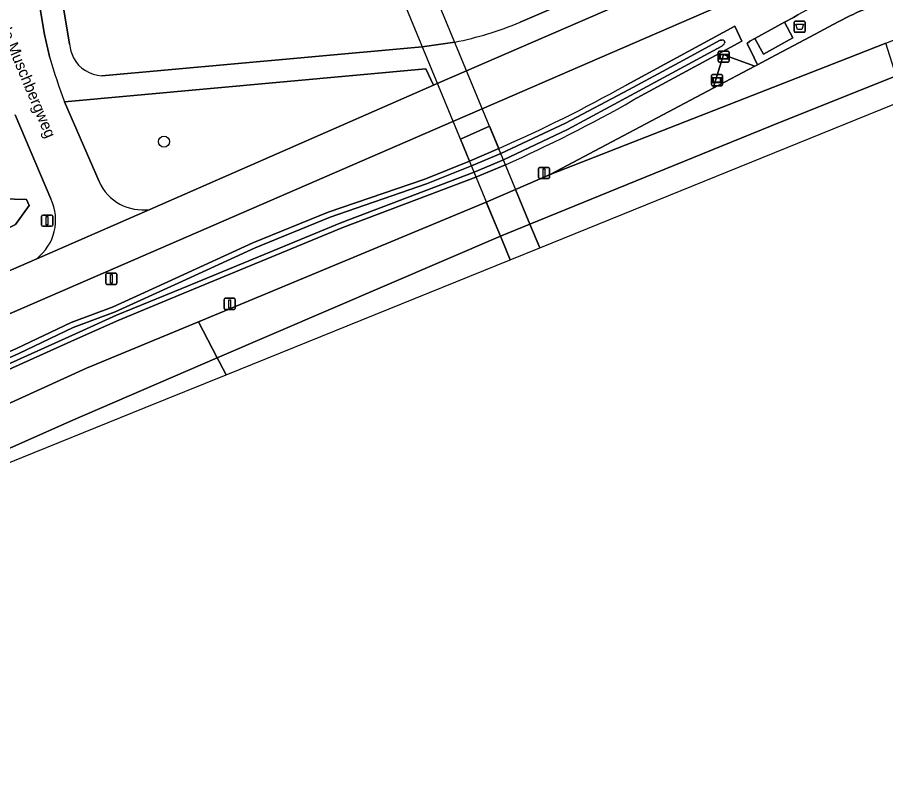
# Model space of a CAD drawing. Extents: x 162722 to 165104, y 384719 to 386284.
# Drawn here: x 164185 to 164262.4, y 384936.5 to 385003.6 of the extents above; entities that cross this region are included whole.
import ezdxf

# ---------------------------------------------------------------- set-up
doc = ezdxf.new("R2010")
doc.units = 0
for name, color, linetype in [('IMGEO_Afvalbak', 7, 'Continuous'), ('IMGEO_Berm_groen', 7, 'Continuous'), ('IMGEO_Boom', 7, 'Continuous'), ('IMGEO_Dek', 7, 'Continuous'), ('IMGEO_Fietspad_gesloten', 7, 'Continuous'), ('IMGEO_Groenvoorziening', 7, 'Continuous'), ('IMGEO_Informatiebord', 7, 'Continuous'), ('IMGEO_Lichtmast', 7, 'Continuous'), ('IMGEO_Oever', 7, 'Continuous'), ('IMGEO_Openbare_ruimte_label', 7, 'Continuous'), ('IMGEO_OVBaan_open', 7, 'Continuous'), ('IMGEO_Pijler', 7, 'Continuous'), ('IMGEO_Rijbaan_lokaal_open', 7, 'Continuous'), ('IMGEO_Rijbaan_regionaal_gesloten', 7, 'Continuous'), ('IMGEO_Verkeersbordpaal', 7, 'Continuous'), ('IMGEO_Voetpad_open', 7, 'Continuous'), ('IMGEO_Waterloop', 7, 'Continuous')]:
    doc.layers.add(name, color=color, linetype=linetype)

msp = doc.modelspace()

# ---------------------------------------------------------------- linework, layer by layer
at = {"layer": 'IMGEO_Afvalbak'}
for p, q in [((164254.24, 385002.368), (164254.24, 385003.168)), ((164254.24, 385003.168), (164254.24, 385002.368)), ((164254.34, 385003.268), (164255.13, 385003.268)), ((164255.13, 385003.268), (164254.34, 385003.268)), ((164255.23, 385003.168), (164255.23, 385002.368)), ((164255.23, 385002.368), (164255.23, 385003.168)), ((164255.13, 385002.268), (164254.34, 385002.268)), ((164254.34, 385002.268), (164255.13, 385002.268))]:
    msp.add_line(p, q, dxfattribs=at)
msp.add_lwpolyline([(164254.383, 385002.982), (164255.087, 385002.982), (164254.938, 385002.512), (164254.532, 385002.512), (164254.383, 385002.982)], dxfattribs=at)
for centre, start, end in [((164254.34, 385003.168), 90, 180), ((164254.34, 385003.168), 90, 180), ((164255.13, 385003.168), 0, 90), ((164255.13, 385003.168), 360, 90), ((164254.34, 385002.368), 180, 270), ((164254.34, 385002.368), 180, 270), ((164255.13, 385002.368), 270, 0), ((164255.13, 385002.368), 270, 0)]:
    msp.add_arc(centre, 0.1, start, end, dxfattribs=at)
at = {"layer": 'IMGEO_Berm_groen'}
for points in [[(164257.459, 385008.904), (164236.917, 385000), (164226.457, 384995.466), (164223.851, 384994.337), (164174.926, 384973.13)], [(164170.65, 384962.991), (164191.19, 384972.345), (164201.175, 384976.496), (164226.817, 384987.156), (164229.43, 384988.27), (164232.508, 384989.603), (164247.035, 384997.295), (164247.859, 385000), (164247.944, 385000.279), (164248.701, 385000), (164250.731, 384999.252), (164250.978, 384999.383), (164250.681, 385000), (164250.064, 385001.28), (164250.281, 385001.478), (164250.744, 385001.727), (164253.379, 385003.161), (164254.17, 385003.591), (164254.584, 385003.832)], [(164239.27, 384997.566), (164243.767, 385000), (164248.945, 385002.803), (164249.58, 385001.482), (164246.849, 385000), (164239.88, 384996.219)], [(164188.037, 384987.425), (164184.844, 384994.922)], [(163914.436, 384836.893), (163949.636, 384856.503), (163973.819, 384869.778), (164000, 384884.149), (164013.236, 384891.063), (164022.225, 384895.944), (164051.682, 384911.299), (164065.065, 384918.062), (164110.825, 384940.537), (164141.781, 384954.8), (164143.407, 384955.639), (164157.246, 384961.665), (164184.977, 384974.098), (164189.827, 384976.411), (164193.585, 384977.81), (164199.165, 384980.364), (164206.029, 384983.505), (164212.733, 384986.251), (164221.342, 384989.201), (164225.31, 384990.805), (164224.511, 384992.738), (164227.098, 384993.913), (164227.922, 384991.919)], [(164228.517, 384990.478), (164225.9, 384989.377), (164214.028, 384984.88), (164199.858, 384979.031), (164194.068, 384976.641), (164190.414, 384974.994), (164164.458, 384963.293), (164143.813, 384954.267), (164142.441, 384953.403), (164125.834, 384945.724), (164092.923, 384929.936), (164061.637, 384914.529), (164036.116, 384901.563), (164011.738, 384888.674), (164000, 384882.305), (163974.591, 384868.517), (163970.141, 384866.102), (163854.543, 384802.202), (163834.335, 384791.252), (163820.765, 384784.53), (163800.899, 384775.69)], [(164029.893, 384905.296), (164057.852, 384919.483), (164097.492, 384939.034), (164124.664, 384953.575), (164138.961, 384960.973), (164173.572, 384976.374), (164186.765, 384982.108)]]:
    msp.add_lwpolyline(points, dxfattribs=at)
msp.add_lwpolyline([(164140.35, 384963.895), (164139.999, 384964.462), (164141.087, 384966.275), (164183.725, 384987.45), (164185.859, 384987.374), (164186.107, 384986.836), (164184.89, 384985.145), (164141.803, 384963.834)], close=True, dxfattribs=at)
for centre, radius, start, end in [((164174.959, 385112.576), 131.769, 293.69908, 299.2127), ((164178.949, 385102.703), 122.685, 293.83045, 299.77868), ((164184.075, 384985.562), 4.378, 307.91124, 25.18045)]:
    msp.add_arc(centre, radius, start, end, dxfattribs=at)
at = {"layer": 'IMGEO_Boom'}
msp.add_circle((164198.104, 384992.531), 0.489, dxfattribs=at)
at = {"layer": 'IMGEO_Dek'}
msp.add_lwpolyline([(164231.573, 384983.081), (164220.787, 385009.193), (164220.592, 385009.115), (164220.399, 385009.469), (164218.209, 385008.591), (164218.345, 385008.216), (164218.15, 385008.138), (164228.941, 384982.015)], close=True, dxfattribs=at)
at = {"layer": 'IMGEO_Fietspad_gesloten'}
msp.add_lwpolyline([(164127.585, 384951.111), (164140.511, 384957.62), (164174.926, 384973.13), (164223.851, 384994.337), (164226.457, 384995.466), (164236.917, 385000), (164257.459, 385008.904), (164259.266, 385009.7), (164257.963, 385012.93), (164249.613, 385009.488), (164247.774, 385008.689), (164227.726, 385000), (164225.061, 384998.845), (164222.455, 384997.716), (164222.114, 384997.568), (164196.835, 384986.501), (164186.765, 384982.108), (164173.572, 384976.374), (164138.961, 384960.973), (164124.664, 384953.575), (164097.492, 384939.034)], dxfattribs=at)
at = {"layer": 'IMGEO_Groenvoorziening'}
for points in [[(164194.294, 385007.945), (164191.639, 385014.785), (164190.662, 385021.427), (164185.711, 385028.348), (164187.966, 385011.698), (164188.163, 385010.392), (164189.7, 385001.218)], [(164229.825, 385003.177), (164255.518, 385014.18)], [(164192.581, 384998.398), (164210.287, 385000), (164221.107, 385000.979), (164224.007, 385001.397)], [(164196.835, 384986.501), (164222.114, 384997.568), (164221.419, 384999.011), (164189.254, 384996.082), (164192.319, 384988.97)]]:
    msp.add_lwpolyline(points, dxfattribs=at)
for centre, radius, start, end in [((164218.363, 385030.243), 29.393, 281.07064, 292.95203), ((164192.699, 385001.412), 3.005, 183.6966, 208.02016), ((164192.712, 385001.412), 3.017, 207.91035, 267.50775), ((164196.205, 384990.713), 4.259, 204.15637, 278.51076)]:
    msp.add_arc(centre, radius, start, end, dxfattribs=at)
at = {"layer": 'IMGEO_Informatiebord'}
for p, q in [((164247.475, 384999.701), (164247.475, 385000.501)), ((164247.475, 385000.501), (164247.475, 384999.701)), ((164247.575, 385000.601), (164248.365, 385000.601)), ((164248.365, 385000.601), (164247.575, 385000.601)), ((164248.465, 385000.501), (164248.465, 384999.701)), ((164248.465, 384999.701), (164248.465, 385000.501)), ((164248.365, 384999.601), (164247.575, 384999.601)), ((164247.575, 384999.601), (164248.365, 384999.601)), ((164246.967, 384998.513), (164247.757, 384998.513)), ((164247.757, 384998.513), (164246.967, 384998.513)), ((164246.867, 384997.613), (164246.867, 384998.413)), ((164246.867, 384998.413), (164246.867, 384997.613)), ((164247.857, 384998.413), (164247.857, 384997.613)), ((164247.857, 384997.613), (164247.857, 384998.413)), ((164247.757, 384997.513), (164246.967, 384997.513)), ((164246.967, 384997.513), (164247.757, 384997.513))]:
    msp.add_line(p, q, dxfattribs=at)
for points in [[(164247.576, 385000.333), (164248.364, 385000.333), (164248.364, 384999.869), (164247.576, 384999.869), (164247.576, 385000.333)], [(164247.641, 385000.268), (164247.641, 384999.934), (164248.299, 384999.934), (164248.299, 385000.268), (164247.641, 385000.268)], [(164246.968, 384998.245), (164247.756, 384998.245), (164247.756, 384997.781), (164246.968, 384997.781), (164246.968, 384998.245)], [(164247.033, 384998.18), (164247.033, 384997.846), (164247.691, 384997.846), (164247.691, 384998.18), (164247.033, 384998.18)]]:
    msp.add_lwpolyline(points, dxfattribs=at)
for centre, start, end in [((164247.575, 385000.501), 90, 180), ((164247.575, 385000.501), 90, 180), ((164248.365, 385000.501), 0, 90), ((164248.365, 385000.501), 360, 90), ((164247.575, 384999.701), 180, 270), ((164247.575, 384999.701), 180, 270), ((164248.365, 384999.701), 270, 0), ((164248.365, 384999.701), 270, 0), ((164246.967, 384998.413), 90, 180), ((164246.967, 384998.413), 90, 180), ((164247.757, 384998.413), 0, 90), ((164247.757, 384998.413), 360, 90), ((164246.967, 384997.613), 180, 270), ((164246.967, 384997.613), 180, 270), ((164247.757, 384997.613), 270, 0), ((164247.757, 384997.613), 270, 0)]:
    msp.add_arc(centre, 0.1, start, end, dxfattribs=at)
at = {"layer": 'IMGEO_Lichtmast'}
for p, q in [((164231.468, 384989.34), (164231.468, 384990.14)), ((164231.468, 384990.14), (164231.468, 384989.34)), ((164231.568, 384990.24), (164232.358, 384990.24)), ((164232.358, 384990.24), (164231.568, 384990.24)), ((164232.458, 384990.14), (164232.458, 384989.34)), ((164232.458, 384989.34), (164232.458, 384990.14)), ((164232.358, 384989.24), (164231.568, 384989.24)), ((164231.568, 384989.24), (164232.358, 384989.24)), ((164203.463, 384977.679), (164203.463, 384978.479)), ((164203.463, 384978.479), (164203.463, 384977.679)), ((164203.563, 384978.579), (164204.353, 384978.579)), ((164204.353, 384978.579), (164203.563, 384978.579)), ((164204.453, 384978.479), (164204.453, 384977.679)), ((164204.453, 384977.679), (164204.453, 384978.479)), ((164204.353, 384977.579), (164203.563, 384977.579)), ((164203.563, 384977.579), (164204.353, 384977.579))]:
    msp.add_line(p, q, dxfattribs=at)
for points in [[(164231.888, 384990.115), (164232.038, 384990.115), (164232.038, 384989.365), (164231.888, 384989.365), (164231.888, 384990.115)], [(164203.883, 384978.454), (164204.033, 384978.454), (164204.033, 384977.704), (164203.883, 384977.704), (164203.883, 384978.454)]]:
    msp.add_lwpolyline(points, dxfattribs=at)
for centre, start, end in [((164231.568, 384990.14), 90, 180), ((164231.568, 384990.14), 90, 180), ((164232.358, 384990.14), 0, 90), ((164232.358, 384990.14), 360, 90), ((164231.568, 384989.34), 180, 270), ((164231.568, 384989.34), 180, 270), ((164232.358, 384989.34), 270, 0), ((164232.358, 384989.34), 270, 0), ((164203.563, 384978.479), 90, 180), ((164203.563, 384978.479), 90, 180), ((164204.353, 384978.479), 0, 90), ((164204.353, 384978.479), 360, 90), ((164203.563, 384977.679), 180, 270), ((164203.563, 384977.679), 180, 270), ((164204.353, 384977.679), 270, 0), ((164204.353, 384977.679), 270, 0)]:
    msp.add_arc(centre, 0.1, start, end, dxfattribs=at)
at = {"layer": 'IMGEO_Oever'}
for points in [[(164239.88, 384996.219), (164246.849, 385000), (164249.58, 385001.482), (164248.945, 385002.803), (164243.767, 385000), (164239.27, 384997.566)], [(164111.025, 384940.117), (164141.985, 384954.382), (164143.607, 384955.219), (164157.434, 384961.24), (164185.172, 384973.676), (164190.008, 384975.983), (164193.763, 384977.38), (164199.358, 384979.941), (164206.214, 384983.078), (164212.897, 384985.816), (164221.505, 384988.765), (164225.487, 384990.375), (164228.1, 384991.49), (164233.871, 384994.19), (164239.489, 384997.156), (164243.988, 384999.591), (164247.662, 385001.561)], [(164247.662, 385001.561), (164247.803, 385001.583)], [(164247.925, 385001.148), (164247.808, 385001.049), (164246.627, 385000.409), (164239.659, 384996.628), (164234.063, 384993.616), (164228.34, 384990.908), (164225.722, 384989.807), (164213.857, 384985.312), (164199.681, 384979.461), (164193.884, 384977.068), (164190.223, 384975.418), (164164.269, 384963.718), (164143.595, 384954.679), (164142.219, 384953.812), (164125.636, 384946.145), (164092.72, 384930.354), (164061.429, 384914.945), (164035.902, 384901.976), (164011.519, 384889.084), (163999.778, 384882.714), (163974.369, 384868.926), (163969.918, 384866.51), (163854.32, 384802.61), (163834.121, 384791.665)], [(164248.007, 385001.522), (164248.034, 385001.489), (164248.054, 385001.367), (164248.044, 385001.322)], [(164227.922, 384991.919), (164225.31, 384990.805), (164221.342, 384989.201), (164212.733, 384986.251), (164206.029, 384983.505), (164199.165, 384980.364), (164193.585, 384977.81), (164189.827, 384976.411), (164184.977, 384974.098), (164157.246, 384961.665), (164143.407, 384955.639), (164141.781, 384954.8), (164110.825, 384940.537), (164065.065, 384918.062), (164051.682, 384911.299), (164022.225, 384895.944), (164013.236, 384891.063), (164000, 384884.149), (163973.819, 384869.778), (163949.636, 384856.503), (163914.436, 384836.893), (163845.028, 384798.673)], [(163820.765, 384784.53), (163834.335, 384791.252), (163854.543, 384802.202), (163970.141, 384866.102), (163974.591, 384868.517), (164000, 384882.305), (164011.738, 384888.674), (164036.116, 384901.563), (164061.637, 384914.529), (164092.923, 384929.936), (164125.834, 384945.724), (164142.441, 384953.403), (164143.813, 384954.267), (164164.458, 384963.293), (164190.414, 384974.994), (164194.068, 384976.641), (164199.858, 384979.031), (164214.028, 384984.88), (164225.9, 384989.377), (164228.517, 384990.478)]]:
    msp.add_lwpolyline(points, dxfattribs=at)
msp.add_lwpolyline([(164184.89, 384985.145), (164186.107, 384986.836), (164185.859, 384987.374), (164183.725, 384987.45), (164141.087, 384966.275), (164139.999, 384964.462), (164140.35, 384963.895), (164141.803, 384963.834)], close=True, dxfattribs=at)
for centre, radius, start, end in [((164247.822, 385001.276), 0.308, 53.11048, 93.59413), ((164247.626, 385001.48), 0.447, 311.99366, 339.26926), ((164174.959, 385112.576), 131.769, 293.69908, 299.2127), ((164178.949, 385102.703), 122.685, 293.83045, 299.77868)]:
    msp.add_arc(centre, radius, start, end, dxfattribs=at)
at = {"layer": 'IMGEO_OVBaan_open'}
msp.add_lwpolyline([(164315.991, 385022.994), (164302.135, 385020.516), (164301.091, 385020.109), (164259.951, 385004.08), (164259.717, 385003.972), (164259.485, 385003.862), (164259.265, 385003.756), (164258.149, 385003.191), (164255.663, 385001.87), (164252.143, 385000), (164250.978, 384999.383), (164250.731, 384999.252), (164247.035, 384997.295), (164232.508, 384989.603), (164259.079, 385000), (164262.419, 385001.307), (164316.75, 385022.567)], dxfattribs=at)
at = {"layer": 'IMGEO_Pijler'}
msp.add_lwpolyline([(164227.098, 384993.913), (164224.511, 384992.738), (164225.31, 384990.805), (164227.922, 384991.919)], close=True, dxfattribs=at)
at = {"layer": 'IMGEO_Rijbaan_lokaal_open'}
for points in [[(164187.944, 385000), (164187.912, 385000.116), (164187.455, 385002.075), (164186.302, 385008.984), (164186.008, 385010.939), (164182.887, 385033.916), (164182.344, 385037.749), (164181.88, 385041.344), (164177.4, 385040.717), (164178.428, 385033.257), (164181.635, 385009.691), (164181.797, 385008.559), (164182.287, 385003.976), (164183.266, 385000)], [(164192.319, 384988.97), (164189.254, 384996.082)], [(164184.844, 384994.922), (164188.037, 384987.425)], [(164186.765, 384982.108), (164196.835, 384986.501)]]:
    msp.add_lwpolyline(points, dxfattribs=at)
for centre, radius, start, end in [((164228.563, 385011.403), 42.189, 195.68124, 201.29391), ((164196.205, 384990.713), 4.259, 204.15637, 278.51076), ((164184.075, 384985.562), 4.378, 307.91124, 25.18045)]:
    msp.add_arc(centre, radius, start, end, dxfattribs=at)
at = {"layer": 'IMGEO_Rijbaan_regionaal_gesloten'}
for points in [[(164263.334, 384998.39), (164262.419, 385001.307), (164259.079, 385000), (164232.508, 384989.603), (164229.43, 384988.27), (164230.704, 384985.185), (164240.977, 384989.371), (164252.127, 384993.919)], [(164231.573, 384983.081), (164264.016, 384996.217), (164263.334, 384998.39), (164252.127, 384993.919), (164240.977, 384989.371), (164230.704, 384985.185)], [(164229.43, 384988.27), (164226.817, 384987.156), (164228.079, 384984.101), (164230.704, 384985.185)], [(164228.079, 384984.101), (164226.817, 384987.156), (164201.175, 384976.496), (164202.848, 384973.275)], [(164231.573, 384983.081), (164230.704, 384985.185), (164228.079, 384984.101), (164228.222, 384983.755), (164228.941, 384982.015)], [(164228.941, 384982.015), (164228.222, 384983.755), (164228.079, 384984.101), (164202.848, 384973.275), (164203.022, 384972.94), (164203.632, 384971.767)], [(163834.886, 384781.879), (164031.014, 384890.049), (164139.093, 384942.782), (164173.473, 384959.556), (164196.428, 384968.85), (164203.632, 384971.767), (164203.022, 384972.94), (164202.848, 384973.275), (164189.764, 384967.635), (164164.509, 384956.406), (164136.448, 384943.995), (164077.479, 384915.27), (164051.634, 384902.415), (163978.153, 384862.695), (163978.101, 384862.667), (163880.927, 384809.18), (163846.958, 384790.267), (163834.094, 384783.248)]]:
    msp.add_lwpolyline(points, close=True, dxfattribs=at)
msp.add_lwpolyline([(163846.958, 384790.267), (163880.927, 384809.18), (163978.101, 384862.667), (163978.153, 384862.695), (164051.634, 384902.415), (164077.479, 384915.27), (164136.448, 384943.995), (164164.509, 384956.406), (164189.764, 384967.635), (164202.848, 384973.275), (164201.175, 384976.496), (164191.19, 384972.345), (164170.65, 384962.991), (164161.969, 384959.269), (164142.262, 384950.403), (164139.038, 384948.773), (164098.314, 384929.568), (164068.299, 384914.743), (164040.026, 384900.418), (164010.013, 384884.532), (164000, 384879.089), (163988.462, 384872.626), (163976.198, 384865.89), (163832.079, 384786.732)], dxfattribs=at)
at = {"layer": 'IMGEO_Verkeersbordpaal'}
for p, q in [((164187.201, 384985.095), (164187.201, 384985.895)), ((164187.201, 384985.895), (164187.201, 384985.095)), ((164187.301, 384985.995), (164188.091, 384985.995)), ((164188.091, 384985.995), (164187.301, 384985.995)), ((164188.191, 384985.895), (164188.191, 384985.095)), ((164188.191, 384985.095), (164188.191, 384985.895)), ((164188.091, 384984.995), (164187.301, 384984.995)), ((164187.301, 384984.995), (164188.091, 384984.995)), ((164192.913, 384979.917), (164192.913, 384980.717)), ((164192.913, 384980.717), (164192.913, 384979.917)), ((164193.013, 384980.817), (164193.803, 384980.817)), ((164193.803, 384980.817), (164193.013, 384980.817)), ((164193.903, 384980.717), (164193.903, 384979.917)), ((164193.903, 384979.917), (164193.903, 384980.717)), ((164193.803, 384979.817), (164193.013, 384979.817)), ((164193.013, 384979.817), (164193.803, 384979.817))]:
    msp.add_line(p, q, dxfattribs=at)
for points in [[(164187.621, 384985.87), (164187.771, 384985.87), (164187.771, 384985.12), (164187.621, 384985.12), (164187.621, 384985.87)], [(164193.333, 384980.692), (164193.483, 384980.692), (164193.483, 384979.942), (164193.333, 384979.942), (164193.333, 384980.692)]]:
    msp.add_lwpolyline(points, dxfattribs=at)
for centre, start, end in [((164187.301, 384985.895), 90, 180), ((164187.301, 384985.895), 90, 180), ((164188.091, 384985.895), 0, 90), ((164188.091, 384985.895), 360, 90), ((164187.301, 384985.095), 180, 270), ((164187.301, 384985.095), 180, 270), ((164188.091, 384985.095), 270, 0), ((164188.091, 384985.095), 270, 0), ((164193.013, 384980.717), 90, 180), ((164193.013, 384980.717), 90, 180), ((164193.803, 384980.717), 0, 90), ((164193.803, 384980.717), 360, 90), ((164193.013, 384979.917), 180, 270), ((164193.013, 384979.917), 180, 270), ((164193.803, 384979.917), 270, 0), ((164193.803, 384979.917), 270, 0)]:
    msp.add_arc(centre, 0.1, start, end, dxfattribs=at)
at = {"layer": 'IMGEO_Voetpad_open'}
for points in [[(164189.7, 385001.218), (164188.163, 385010.392), (164187.966, 385011.698), (164185.711, 385028.348), (164185.242, 385031.707), (164182.887, 385033.916), (164186.008, 385010.939), (164186.302, 385008.984), (164187.455, 385002.075), (164187.912, 385000.116), (164187.944, 385000)], [(164265.125, 385009.075), (164260.276, 385007.195), (164259.266, 385009.7), (164257.459, 385008.904), (164258.621, 385006.012), (164254.584, 385003.832), (164254.17, 385003.591), (164253.379, 385003.161), (164254.138, 385001.766), (164251.503, 385000.332), (164250.744, 385001.727), (164250.281, 385001.478), (164250.064, 385001.28), (164250.681, 385000), (164250.978, 384999.383), (164252.143, 385000), (164255.663, 385001.87), (164258.149, 385003.191), (164259.265, 385003.756), (164259.485, 385003.862), (164259.717, 385003.972), (164259.951, 385004.08), (164301.091, 385020.109)], [(164247.774, 385008.689), (164249.613, 385009.488), (164257.963, 385012.93), (164257.182, 385014.893), (164255.518, 385014.18), (164229.825, 385003.177)], [(164189.254, 384996.082), (164221.419, 384999.011), (164222.114, 384997.568), (164222.455, 384997.716), (164225.061, 384998.845), (164227.726, 385000), (164247.774, 385008.689)], [(164224.007, 385001.397), (164221.107, 385000.979), (164210.287, 385000), (164192.581, 384998.398)]]:
    msp.add_lwpolyline(points, dxfattribs=at)
for points in [[(164231.573, 384983.081), (164220.787, 385009.193), (164220.592, 385009.115), (164220.399, 385009.469), (164218.209, 385008.591), (164218.345, 385008.216), (164218.15, 385008.138), (164228.941, 384982.015)], [(164253.379, 385003.161), (164250.744, 385001.727), (164251.503, 385000.332), (164254.138, 385001.766)], [(164250.731, 384999.252), (164248.701, 385000), (164247.944, 385000.279), (164247.859, 385000), (164247.035, 384997.295)]]:
    msp.add_lwpolyline(points, close=True, dxfattribs=at)
for centre, radius, start, end in [((164218.363, 385030.243), 29.393, 281.07064, 292.95203), ((164192.699, 385001.412), 3.005, 183.6966, 208.02016), ((164228.563, 385011.403), 42.189, 195.68124, 201.29391), ((164192.712, 385001.412), 3.017, 207.91035, 267.50775)]:
    msp.add_arc(centre, radius, start, end, dxfattribs=at)
at = {"layer": 'IMGEO_Waterloop'}
for points in [[(164247.803, 385001.583), (164247.662, 385001.561), (164243.988, 384999.591), (164239.489, 384997.156), (164233.871, 384994.19), (164228.1, 384991.49), (164225.487, 384990.375), (164221.505, 384988.765), (164212.897, 384985.816), (164206.214, 384983.078), (164199.358, 384979.941), (164193.763, 384977.38), (164190.008, 384975.983), (164185.172, 384973.676), (164157.434, 384961.24), (164143.607, 384955.219), (164141.985, 384954.382), (164111.025, 384940.117)], [(163834.121, 384791.665), (163854.32, 384802.61), (163969.918, 384866.51), (163974.369, 384868.926), (163999.778, 384882.714), (164011.519, 384889.084), (164035.902, 384901.976), (164061.429, 384914.945), (164092.72, 384930.354), (164125.636, 384946.145), (164142.219, 384953.812), (164143.595, 384954.679), (164164.269, 384963.718), (164190.223, 384975.418), (164193.884, 384977.068), (164199.681, 384979.461), (164213.857, 384985.312), (164225.722, 384989.807), (164228.34, 384990.908), (164234.063, 384993.616), (164239.659, 384996.628), (164246.627, 385000.409), (164247.808, 385001.049)], [(164247.808, 385001.049), (164247.925, 385001.148)], [(164248.044, 385001.322), (164248.054, 385001.367), (164248.034, 385001.489), (164248.007, 385001.522)]]:
    msp.add_lwpolyline(points, dxfattribs=at)
for centre, radius, start, end in [((164247.822, 385001.276), 0.308, 53.11048, 93.59413), ((164247.626, 385001.48), 0.447, 311.99366, 339.26926)]:
    msp.add_arc(centre, radius, start, end, dxfattribs=at)

# ---------------------------------------------------------------- texts
at = {"layer": 'IMGEO_Openbare_ruimte_label'}
msp.add_text('Oude Muschbergweg', height=1, rotation=292.6419, dxfattribs=at).set_placement((164182.703, 385004.486))

doc.saveas('drawing.dxf')
